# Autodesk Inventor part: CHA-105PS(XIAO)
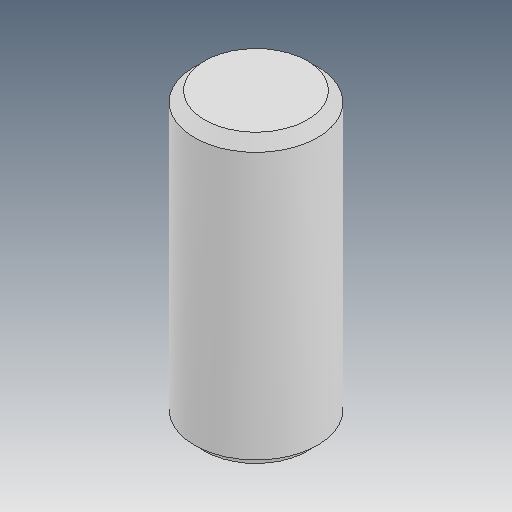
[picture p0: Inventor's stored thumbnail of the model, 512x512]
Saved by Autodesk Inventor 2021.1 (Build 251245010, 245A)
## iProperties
Created: 2021-05
Part Number: CHA-105PS(XIAO)
Material: Ogólny
Document SubType Name: Modeling
Designer: user
Density: 1 g/cm^3
Appearance: Domyślna
Author: user
Revision Number: ÈÎºÎ
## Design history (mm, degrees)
feature "µ¹½Ç1"
node "Bryła1"
